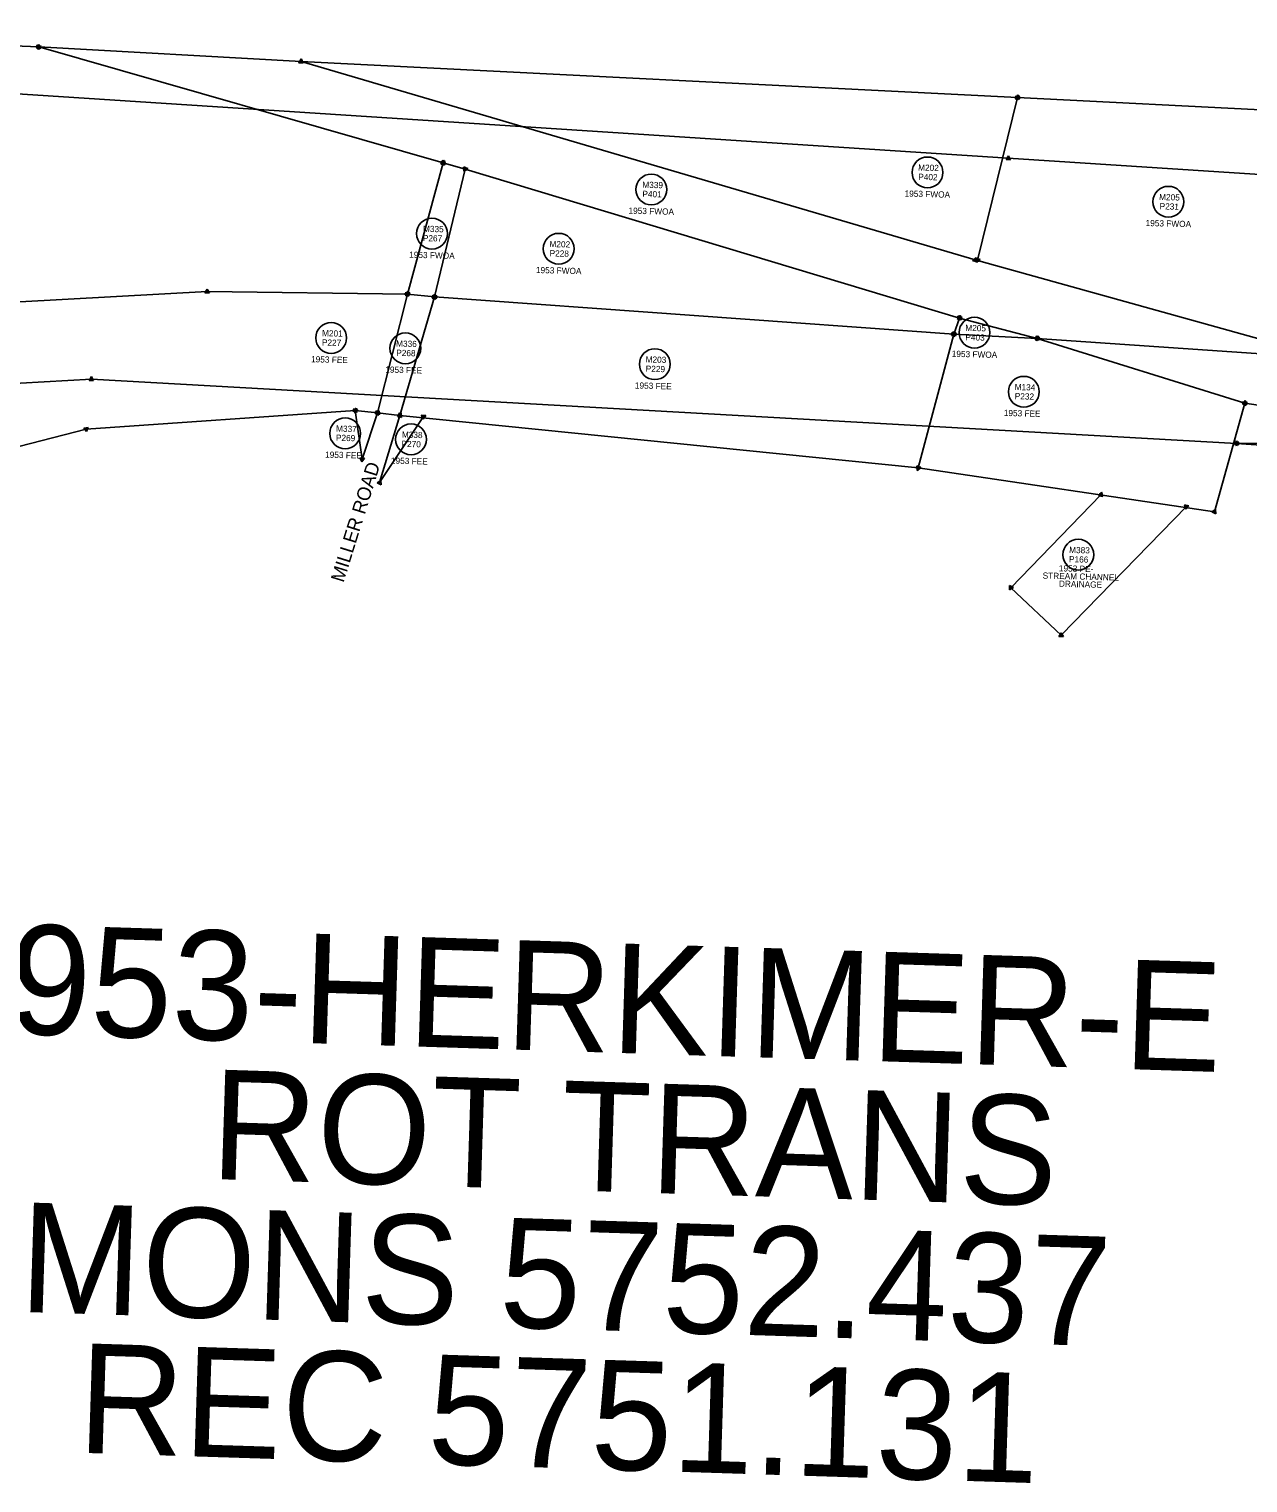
# Model space of a CAD drawing. Extents: x 325029 to 414988, y 1517527 to 1550420.
# Drawn here: x 374498 to 375533, y 1522300 to 1523534 of the extents above; entities that cross this region are included whole.
import ezdxf

# ---------------------------------------------------------------- set-up
doc = ezdxf.new("R2010")
doc.units = 0
for name, color, linetype in [('Level 56', 7, 'Continuous'), ('MEE', 7, 'Continuous'), ('MHB', 7, 'Continuous'), ('MHBWOA', 7, 'Continuous'), ('MRBL1', 7, 'Continuous'), ('MRBL2', 7, 'Continuous'), ('NNSH_P_T', 7, 'Continuous'), ('S_C', 7, 'Continuous')]:
    doc.layers.add(name, color=color, linetype=linetype)

msp = doc.modelspace()

# ---------------------------------------------------------------- linework, layer by layer
at = {"layer": 'Level 56'}
for centre in [(375260.6, 1523412.8), (375026.1, 1523398.3), (375465.1, 1523387.9), (374839.9, 1523360.9), (374947.5, 1523348), (375300.5, 1523276.8), (374754.3, 1523272.3), (374817.3, 1523263.5), (375029.1, 1523250), (375342.4, 1523226.6), (374766.2, 1523191.3), (374822.1, 1523186.2), (375388.6, 1523088.3)]:
    msp.add_circle(centre, 13.1, dxfattribs=at)
at = {"layer": 'MEE'}
for p, q in [((375407.8, 1523139.2), (375331.3, 1523060.3)), ((375374.1, 1523019.9), (375480.4, 1523129.1)), ((375331.3, 1523060.3), (375374.1, 1523019.9))]:
    msp.add_line(p, q, dxfattribs=at)
for points in [[(375405.7, 1523138.6), (375408.3, 1523141.3)], [(375409.4, 1523137.7), (375405.7, 1523138.6)], [(375408.3, 1523141.3), (375409.4, 1523137.7)], [(375479.8, 1523127), (375478.8, 1523130.6)], [(375478.8, 1523130.6), (375482.5, 1523129.7)], [(375482.5, 1523129.7), (375479.8, 1523127)], [(375330.1, 1523062.2), (375333.5, 1523060.4)], [(375330.2, 1523058.4), (375330.1, 1523062.2)], [(375333.5, 1523060.4), (375330.2, 1523058.4)], [(375372.2, 1523018.8), (375374, 1523022.1)], [(375376, 1523018.8), (375372.2, 1523018.8)], [(375374, 1523022.1), (375376, 1523018.8)]]:
    msp.add_lwpolyline(points, dxfattribs=at)
for centre, radius in [((375407.8, 1523139.2), 1.09), ((375480.4, 1523129.1), 1.09), ((375331.3, 1523060.3), 0.227), ((375374.1, 1523019.9), 0.227)]:
    msp.add_circle(centre, radius, dxfattribs=at)
at = {"layer": 'MHB'}
for p, q in [((374490, 1523302.9), (374648.9, 1523311.6)), ((374819.2, 1523309.6), (374793.7, 1523208.7)), ((374842.1, 1523307.1), (374812.6, 1523206.6)), ((375282.9, 1523275.5), (375353.8, 1523271.9)), ((375353.8, 1523271.9), (375530, 1523216.9)), ((375530, 1523216.9), (375504.2, 1523124.8)), ((375530, 1523216.9), (375838.6, 1523172)), ((374774.8, 1523210.7), (374546.3, 1523195)), ((374793.7, 1523208.7), (374774.8, 1523210.7)), ((374780.5, 1523169.3), (374774.8, 1523210.7)), ((374793.7, 1523208.7), (374780.5, 1523169.3)), ((374812.6, 1523206.6), (374793.7, 1523208.7)), ((374812.6, 1523206.6), (374795.4, 1523149.5)), ((374795.4, 1523149.5), (374832.6, 1523205.5)), ((374546.3, 1523195), (374333.9, 1523140.4)), ((375835.7, 1523160.9), (375523, 1523182.8)), ((375504.2, 1523124.8), (375252.8, 1523161.9))]:
    msp.add_line(p, q, dxfattribs=at)
for points in [[(374647.1, 1523310.5), (374648.9, 1523313.8)], [(374650.9, 1523310.6), (374647.1, 1523310.5)], [(374648.9, 1523313.8), (374650.9, 1523310.6)], [(374817.1, 1523310.4), (374820.9, 1523310.9)], [(374819.5, 1523307.4), (374817.1, 1523310.4)], [(374817.2, 1523308.7), (374819.4, 1523311.8)], [(374819.4, 1523311.8), (374820.9, 1523308.3)], [(374820.9, 1523310.9), (374819.5, 1523307.4)], [(374820.9, 1523308.3), (374817.2, 1523308.7)], [(374840.1, 1523308.1), (374843.9, 1523308.3)], [(374842.2, 1523304.9), (374840.1, 1523308.1)], [(374843.9, 1523308.3), (374842.2, 1523304.9)], [(375281, 1523274.5), (375283, 1523277.7)], [(375284.8, 1523274.3), (375281, 1523274.5)], [(375283, 1523277.7), (375284.8, 1523274.3)], [(375351.8, 1523271.2), (375354.2, 1523274.1)], [(375354.2, 1523274.1), (375355.5, 1523270.5)], [(375355.5, 1523270.5), (375351.8, 1523271.2)], [(374772.7, 1523210.4), (374775.6, 1523212.7)], [(374774.8, 1523208.6), (374773, 1523211.9)], [(374773, 1523211.9), (374776.7, 1523211.8)], [(374776.7, 1523211.8), (374774.8, 1523208.6)], [(374775.6, 1523212.7), (374776.2, 1523209)], [(375528, 1523216.1), (375530.3, 1523219.1)], [(375531.7, 1523215.6), (375528, 1523216.1)], [(375528.1, 1523218), (375531.9, 1523217.9)], [(375529.9, 1523214.7), (375528.1, 1523218)], [(375531.9, 1523217.9), (375529.9, 1523214.7)], [(375530.3, 1523219.1), (375531.7, 1523215.6)], [(374776.2, 1523209), (374772.7, 1523210.4)], [(374791.6, 1523208.5), (374794.7, 1523210.6)], [(374795, 1523206.9), (374791.6, 1523208.5)], [(374793.5, 1523206.5), (374792, 1523210)], [(374792, 1523210), (374795.7, 1523209.5)], [(374792.1, 1523207.2), (374793.3, 1523210.8)], [(374795.8, 1523208), (374792.1, 1523207.2)], [(374793.3, 1523210.8), (374795.8, 1523208)], [(374795.7, 1523209.5), (374793.5, 1523206.5)], [(374794.7, 1523210.6), (374795, 1523206.9)], [(374810.5, 1523206.5), (374813.6, 1523208.6)], [(374813.9, 1523204.8), (374810.5, 1523206.5)], [(374811.1, 1523205.1), (374812.1, 1523208.7)], [(374814.7, 1523206), (374811.1, 1523205.1)], [(374812.1, 1523208.7), (374814.7, 1523206)], [(374813.6, 1523208.6), (374813.9, 1523204.8)], [(374832.5, 1523203.3), (374830.8, 1523206.7)], [(374830.8, 1523206.7), (374834.6, 1523206.5)], [(374834.6, 1523206.5), (374832.5, 1523203.3)], [(374544.2, 1523195.8), (374547.9, 1523196.4)], [(374546.6, 1523192.9), (374544.2, 1523195.8)], [(374547.9, 1523196.4), (374546.6, 1523192.9)], [(375522.9, 1523180.6), (375521.2, 1523184)], [(375521.2, 1523184), (375525, 1523183.8)], [(375525, 1523183.8), (375522.9, 1523180.6)], [(374780.3, 1523167.2), (374778.7, 1523170.6)], [(374778.7, 1523170.6), (374782.5, 1523170.3)], [(374782.5, 1523170.3), (374780.3, 1523167.2)], [(375252.5, 1523159.7), (375251.1, 1523163.3)], [(375251.1, 1523163.3), (375254.9, 1523162.7)], [(375254.9, 1523162.7), (375252.5, 1523159.7)], [(374793.3, 1523149.3), (374796.4, 1523151.4)], [(374796.4, 1523151.4), (374796.7, 1523147.7)], [(374796.7, 1523147.7), (374793.3, 1523149.3)], [(375502, 1523124.7), (375505.1, 1523126.7)], [(375505.1, 1523126.7), (375505.3, 1523122.9)], [(375505.3, 1523122.9), (375502, 1523124.7)]]:
    msp.add_lwpolyline(points, dxfattribs=at)
for centre, radius in [((374648.9, 1523311.6), 0.227), ((374819.2, 1523309.6), 1.09), ((374819.2, 1523309.6), 0.227), ((374842.1, 1523307.1), 0.227), ((375282.9, 1523275.5), 1.09), ((375353.8, 1523271.9), 0.227), ((374774.8, 1523210.7), 1.09), ((375530, 1523216.9), 1.09), ((375530, 1523216.9), 0.227), ((374774.8, 1523210.7), 0.227), ((374793.7, 1523208.7), 1.09), ((374793.7, 1523208.7), 1.09), ((374793.7, 1523208.7), 0.227), ((374812.6, 1523206.6), 1.09), ((374812.6, 1523206.6), 0.227), ((374832.6, 1523205.5), 1.09), ((374546.3, 1523195), 0.227), ((375523, 1523182.8), 1.09), ((374780.5, 1523169.3), 0.227), ((375252.8, 1523161.9), 1.09), ((374795.4, 1523149.5), 0.227), ((375504.2, 1523124.8), 0.227)]:
    msp.add_circle(centre, radius, dxfattribs=at)
at = {"layer": 'MHBWOA'}
for p, q in [((374506.1, 1523519.3), (374179.4, 1523534.5)), ((374506.1, 1523519.3), (374728.7, 1523506.9)), ((374849.4, 1523420.9), (374506.1, 1523519.3)), ((374728.7, 1523506.9), (375337.1, 1523476.4)), ((374728.7, 1523506.9), (375301, 1523338.5)), ((375337.1, 1523476.4), (375303, 1523338.3)), ((375337.1, 1523476.4), (375626.7, 1523461.7)), ((374849.4, 1523420.9), (374819.2, 1523309.6)), ((374842.1, 1523307.1), (374868.1, 1523415.7)), ((374868.1, 1523415.7), (374849.4, 1523420.9)), ((375287.8, 1523289.2), (374868.1, 1523415.7)), ((375301, 1523338.5), (375568.8, 1523264)), ((374648.9, 1523311.6), (374819.2, 1523309.6)), ((374819.2, 1523309.6), (374842.1, 1523307.1)), ((375282.9, 1523275.5), (374842.1, 1523307.1)), ((375287.8, 1523289.2), (375282.9, 1523275.5)), ((375353.8, 1523271.9), (375287.8, 1523289.2)), ((375252.8, 1523161.9), (375282.9, 1523275.5)), ((375602.3, 1523254.8), (375353.8, 1523271.9)), ((374812.6, 1523206.6), (375252.8, 1523161.9))]:
    msp.add_line(p, q, dxfattribs=at)
for points in [[(374504.1, 1523518.3), (374506.2, 1523521.5)], [(374505.7, 1523517.2), (374504.4, 1523520.7)], [(374504.4, 1523520.7), (374508.1, 1523520.1)], [(374505.5, 1523517.2), (374504.6, 1523520.9)], [(374504.6, 1523520.9), (374508.2, 1523519.8)], [(374508.1, 1523520.1), (374505.7, 1523517.2)], [(374506.2, 1523521.5), (374507.9, 1523518.1)], [(374507.9, 1523518.1), (374504.1, 1523518.3)], [(374508.2, 1523519.8), (374505.5, 1523517.2)], [(374726.7, 1523506.1), (374729.1, 1523509)], [(374726.8, 1523505.9), (374728.9, 1523509.1)], [(374728.9, 1523509.1), (374730.6, 1523505.7)], [(374729.1, 1523509), (374730.4, 1523505.5)], [(374730.4, 1523505.5), (374726.7, 1523506.1)], [(374730.6, 1523505.7), (374726.8, 1523505.9)], [(375335, 1523477.3), (375338.8, 1523477.7)], [(375337.3, 1523474.3), (375335, 1523477.3)], [(375335.1, 1523475.4), (375337.2, 1523478.6)], [(375338.9, 1523475.2), (375335.1, 1523475.4)], [(375337.2, 1523478.6), (375338.9, 1523475.2)], [(375338.8, 1523477.7), (375337.3, 1523474.3)], [(374847.3, 1523420.9), (374850.5, 1523422.8)], [(374847.5, 1523419.8), (374849.5, 1523423.1)], [(374848.8, 1523418.8), (374847.9, 1523422.5)], [(374847.9, 1523422.5), (374851.5, 1523421.4)], [(374851.5, 1523421.4), (374848.8, 1523418.8)], [(374849.5, 1523423.1), (374851.3, 1523419.8)], [(374850.5, 1523422.8), (374850.5, 1523419)], [(374850.5, 1523419), (374847.3, 1523420.9)], [(374851.3, 1523419.8), (374847.5, 1523419.8)], [(374867.5, 1523413.6), (374866.6, 1523417.2)], [(374866.6, 1523417.2), (374870.2, 1523416.2)], [(374867.5, 1523413.6), (374866.6, 1523417.2)], [(374866.6, 1523417.2), (374870.3, 1523416.2)], [(374867, 1523413.8), (374867.1, 1523417.6)], [(374870.3, 1523415.7), (374867, 1523413.8)], [(374867.1, 1523417.6), (374870.3, 1523415.7)], [(374870.2, 1523416.2), (374867.5, 1523413.6)], [(374870.3, 1523416.2), (374867.5, 1523413.6)], [(375298.9, 1523337.9), (375301.6, 1523340.6)], [(375302.6, 1523336.9), (375298.9, 1523337.9)], [(375301.5, 1523336.8), (375302.4, 1523340.4)], [(375302.5, 1523336.3), (375301.5, 1523339.9)], [(375301.5, 1523339.9), (375305.2, 1523338.9)], [(375305.2, 1523337.8), (375301.5, 1523336.8)], [(375301.6, 1523340.6), (375302.6, 1523336.9)], [(375302.4, 1523340.4), (375305.2, 1523337.8)], [(375305.2, 1523338.9), (375302.5, 1523336.3)], [(374647.1, 1523310.5), (374648.9, 1523313.8)], [(374650.9, 1523310.6), (374647.1, 1523310.5)], [(374648.9, 1523313.8), (374650.9, 1523310.6)], [(374817.2, 1523310.6), (374821, 1523310.8)], [(374819.3, 1523307.4), (374817.2, 1523310.6)], [(374818.3, 1523307.6), (374817.9, 1523311.3)], [(374817.9, 1523311.3), (374821.3, 1523309.9)], [(374821, 1523310.8), (374819.3, 1523307.4)], [(374821.3, 1523309.9), (374818.3, 1523307.6)], [(374840.1, 1523306.2), (374842.3, 1523309.3)], [(374843.8, 1523305.8), (374840.1, 1523306.2)], [(374841.9, 1523305), (374840.2, 1523308.3)], [(374840.2, 1523308.3), (374844, 1523308.1)], [(374840.3, 1523305.8), (374841.8, 1523309.3)], [(374844.1, 1523306.2), (374840.3, 1523305.8)], [(374841.8, 1523309.3), (374844.1, 1523306.2)], [(374844, 1523308.1), (374841.9, 1523305)], [(374842.3, 1523309.3), (374843.8, 1523305.8)], [(375285.7, 1523288.7), (375288.5, 1523291.3)], [(375285.7, 1523288.7), (375288.4, 1523291.3)], [(375289.3, 1523287.6), (375285.7, 1523288.7)], [(375289.4, 1523287.7), (375285.7, 1523288.7)], [(375286.2, 1523287.8), (375287.4, 1523291.4)], [(375289.9, 1523288.5), (375286.2, 1523287.8)], [(375287.2, 1523287.1), (375286.3, 1523290.8)], [(375286.3, 1523290.8), (375289.9, 1523289.8)], [(375289.9, 1523289.8), (375287.2, 1523287.1)], [(375287.4, 1523291.4), (375289.9, 1523288.5)], [(375288.4, 1523291.3), (375289.4, 1523287.7)], [(375288.5, 1523291.3), (375289.3, 1523287.6)], [(375280.8, 1523275.4), (375283.9, 1523277.5)], [(375284.1, 1523273.7), (375280.8, 1523275.4)], [(375282.8, 1523273.3), (375281.1, 1523276.7)], [(375281.1, 1523276.7), (375284.9, 1523276.5)], [(375281.2, 1523274.3), (375282.7, 1523277.7)], [(375284.9, 1523274.6), (375281.2, 1523274.3)], [(375282.7, 1523277.7), (375284.9, 1523274.6)], [(375284.9, 1523276.5), (375282.8, 1523273.3)], [(375283.9, 1523277.5), (375284.1, 1523273.7)], [(375353.5, 1523269.8), (375352.2, 1523273.3)], [(375352.2, 1523273.3), (375355.9, 1523272.7)], [(375352.5, 1523270.2), (375353.1, 1523274)], [(375353.1, 1523274), (375356, 1523271.6)], [(375356, 1523271.6), (375352.5, 1523270.2)], [(375355.9, 1523272.7), (375353.5, 1523269.8)], [(374810.7, 1523205.7), (374812.9, 1523208.8)], [(374814.4, 1523205.3), (374810.7, 1523205.7)], [(374812.9, 1523208.8), (374814.4, 1523205.3)], [(375251.9, 1523159.9), (375251.6, 1523163.7)], [(375251.6, 1523163.7), (375255, 1523162.1)], [(375255, 1523162.1), (375251.9, 1523159.9)]]:
    msp.add_lwpolyline(points, dxfattribs=at)
for centre, radius in [((374506.1, 1523519.3), 1.09), ((374506.1, 1523519.3), 1.09), ((374506.1, 1523519.3), 0.227), ((374728.7, 1523506.9), 1.09), ((374728.7, 1523506.9), 0.227), ((375337.1, 1523476.4), 1.09), ((375337.1, 1523476.4), 0.227), ((374849.4, 1523420.9), 0.227), ((374849.4, 1523420.9), 0.227), ((374849.4, 1523420.9), 0.227), ((374868.1, 1523415.7), 1.09), ((374868.1, 1523415.7), 0.227), ((374868.1, 1523415.7), 0.227), ((375301, 1523338.5), 0.227), ((375303, 1523338.3), 1.09), ((375303, 1523338.3), 1.09), ((374648.9, 1523311.6), 0.227), ((374819.2, 1523309.6), 0.227), ((374819.2, 1523309.6), 0.227), ((374842.1, 1523307.1), 1.09), ((374842.1, 1523307.1), 1.09), ((374842.1, 1523307.1), 0.227), ((375287.8, 1523289.2), 1.09), ((375287.8, 1523289.2), 1.09), ((375287.8, 1523289.2), 1.09), ((375287.8, 1523289.2), 0.227), ((375282.9, 1523275.5), 1.09), ((375282.9, 1523275.5), 0.227), ((375282.9, 1523275.5), 0.227), ((375353.8, 1523271.9), 0.227), ((375353.8, 1523271.9), 0.227), ((374812.7, 1523206.6), 1.09), ((375252.8, 1523161.9), 0.227)]:
    msp.add_circle(centre, radius, dxfattribs=at)
at = {"layer": 'MRBL1'}
for p, q in [((374372.4, 1523486.9), (375329.2, 1523424.8)), ((375329.2, 1523424.8), (375705.3, 1523400.4))]:
    msp.add_line(p, q, dxfattribs=at)
for points in [[(375327.3, 1523423.9), (375329.4, 1523427)], [(375331.1, 1523423.6), (375327.3, 1523423.9)], [(375329.4, 1523427), (375331.1, 1523423.6)]]:
    msp.add_lwpolyline(points, dxfattribs=at)
msp.add_circle((375329.2, 1523424.8), 0.227, dxfattribs=at)
at = {"layer": 'MRBL2'}
for p, q in [((374126.6, 1523214.2), (374550.8, 1523237.3)), ((374550.8, 1523237.3), (375523, 1523182.8)), ((375523, 1523182.8), (376086.4, 1523190.2))]:
    msp.add_line(p, q, dxfattribs=at)
for points in [[(374548.9, 1523236.2), (374550.8, 1523239.5)], [(374552.6, 1523236.2), (374548.9, 1523236.2)], [(374550.8, 1523239.5), (374552.6, 1523236.2)], [(375521.1, 1523181.8), (375523, 1523185)], [(375524.9, 1523181.7), (375521.1, 1523181.8)], [(375523, 1523185), (375524.9, 1523181.7)]]:
    msp.add_lwpolyline(points, dxfattribs=at)
for centre in [(374550.8, 1523237.3), (375523, 1523182.8)]:
    msp.add_circle(centre, 0.227, dxfattribs=at)

# ---------------------------------------------------------------- texts
at = {"layer": 'Level 56'}
for s, height, p in [('M202', 5.25, (375252.6, 1523414.4)), ('P402', 5.25, (375252.7, 1523406.5)), ('M339', 5.25, (375018.4, 1523399.8)), ('P401', 5.25, (375018.5, 1523392)), ('1953 FWOA', 5.25, (375241.1, 1523392.3)), ('M205', 5.25, (375457.2, 1523389.4)), ('P231', 5.25, (375457.6, 1523381.5)), ('1953 FWOA', 5.25, (375006.7, 1523377.8)), ('1953 FWOA', 5.25, (375445.7, 1523367.3)), ('M335', 5.25, (374832.2, 1523362.4)), ('P267', 5.25, (374832.1, 1523354.5)), ('M202', 5.25, (374939.6, 1523349.5)), ('1953 FWOA', 5.25, (374820.5, 1523340.4)), ('P228', 5.25, (374939.7, 1523341.6)), ('1953 FWOA', 5.25, (374928.1, 1523327.4)), ('M201', 5.25, (374746.5, 1523273.8)), ('M205', 5.25, (375292.6, 1523278.3)), ('P403', 5.25, (375292.7, 1523270.4)), ('P227', 5.25, (374746.4, 1523265.9)), ('M336', 5.25, (374809.4, 1523265)), ('P268', 5.25, (374809.5, 1523257.1)), ('1953 FWOA', 5.25, (375281.1, 1523256.3)), ('1953 FEE', 5.25, (374737.2, 1523251.7)), ('M203', 5.25, (375021.2, 1523251.5)), ('P229', 5.25, (375021.3, 1523243.6)), ('1953 FEE', 5.25, (374800.2, 1523242.9)), ('1953 FEE', 5.25, (375012.1, 1523229.4)), ('M134', 5.25, (375334.5, 1523228.1)), ('P232', 5.25, (375334.6, 1523220.3)), ('1953 FEE', 5.25, (375325.3, 1523206.1)), ('P269', 5.25, (374758.3, 1523185)), ('M337', 5.25, (374758.4, 1523192.8)), ('M338', 5.25, (374814.3, 1523187.7)), ('1953 FEE', 5.25, (374749.1, 1523170.7)), ('P270', 5.25, (374814, 1523179.8)), ('1953 FEE', 5.25, (374805, 1523165.6)), ('M383', 5.25, (375380.8, 1523089.8)), ('1953 PE-', 5.25, (375372.1, 1523074.2)), ('P166', 5.25, (375380.7, 1523081.9)), ('STREAM CHANNEL', 5.249, (375358.3, 1523068)), ('DRAINAGE', 5.25, (375372.1, 1523061.1))]:
    msp.add_text(s, height=height, rotation=358.4842, dxfattribs=at).set_placement(p)
at = {"layer": 'NNSH_P_T'}
msp.add_text('MILLER ROAD', height=11.626, rotation=72.7229, dxfattribs=at).set_placement((374764.8, 1523064.1))
at = {"layer": 'S_C'}
for s, height, p in [('1953-HERKIMER-E', 93.011, (374410.7, 1522684)), ('ROT TRANS', 93.01, (374651.3, 1522558.4)), ('MONS 5752.437', 93.011, (374488.8, 1522445.6)), ('REC 5751.131', 93.011, (374538.4, 1522326))]:
    msp.add_text(s, height=height, rotation=358.1809, dxfattribs=at).set_placement(p)

doc.saveas('drawing.dxf')
